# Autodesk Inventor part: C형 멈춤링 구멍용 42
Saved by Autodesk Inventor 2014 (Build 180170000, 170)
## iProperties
Created: 2026-04
Part Number: C형 멈춤링 구멍용 42
Material: 강철, 연강
Document SubType Name: Modeling
Designer: dg
Density: 7.86 g/cm^3
Appearance: 강철
Author: jhkim
Description: 리테이닝 링(C형)
Creation Date: 2026-03-27
Sending System: Autodesk Inventor 2026
Preprocessor: ST-DEVELOPER v20.1
Author: dg
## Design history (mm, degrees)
node "C형 멈춤링 구멍용 421"
body "Solid1"
node "기준1"
